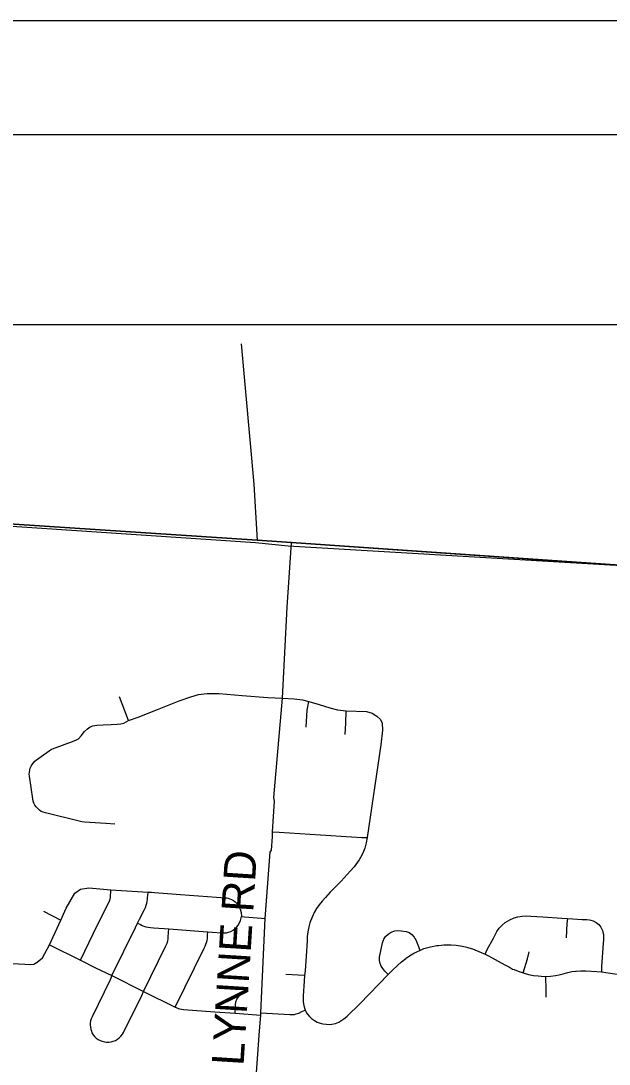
# Model space of a CAD drawing. Extents: x 1880545 to 1948545, y 79309 to 723051.
# Drawn here: x 1911747 to 1916920, y 713881 to 723051 of the extents above; entities that cross this region are included whole.
import ezdxf

# ---------------------------------------------------------------- set-up
doc = ezdxf.new("R2010")
doc.units = 0
for name, color, linetype in [('GM_X_Corporation', 7, 'Continuous'), ('GM_X_Township', 7, 'Continuous'), ('GM_X_Township_Road', 7, 'Continuous'), ('SH_Border', 7, 'Continuous'), ('SH_Cut_Line', 7, 'Continuous'), ('SH_Text', 7, 'Continuous')]:
    doc.layers.add(name, color=color, linetype=linetype)

msp = doc.modelspace()

# ---------------------------------------------------------------- linework, layer by layer
at = {"layer": 'GM_X_Corporation'}
msp.add_lwpolyline([(1919489.4, 720211.7), (1919365.4, 718089.3), (1918484.9, 718152.3), (1917524.9, 718231.9), (1914096.8, 718433.3), (1913810.1, 718462.2), (1910747.9, 718668), (1904355.4, 719097.5), (1898180.5, 719469.3), (1898145.1, 719477.4), (1897456.4, 719506.8), (1897439.2, 719506.5), (1897485.7, 720211.7)], dxfattribs=at)
at = {"layer": 'GM_X_Township'}
for points in [[(1919532.9, 720211.7), (1919386.9, 718084.6), (1918484.9, 718152.3), (1917524.9, 718231.9), (1914126, 718465.8), (1913825.7, 718485.3), (1910748.6, 718688), (1904377.2, 719098.9), (1899877.1, 719377.9), (1898145.1, 719477.4), (1897456.4, 719506.8), (1896833.7, 719533.1), (1896793, 719531.9), (1894774.7, 719644.4), (1893522.1, 719763.2), (1893081.4, 719771.3), (1891817.3, 719823), (1891843, 720211.7)], [(1899877.1, 719377.9), (1904377.2, 719098.9), (1910748.6, 718688), (1913825.7, 718485.3), (1914126, 718465.8), (1917524.9, 718231.9), (1918484.9, 718152.3), (1919386.9, 718084.6), (1922040.5, 717966.3)]]:
    msp.add_lwpolyline(points, dxfattribs=at)
at = {"layer": 'GM_X_Township_Road'}
for p, q in [((1914127.1, 718463), (1913826.9, 718482.5)), ((1917526.1, 718229.1), (1914127.1, 718463)), ((1912694.5, 716901.1), (1912612.8, 717111.1)), ((1911946.4, 715226.6), (1912098.8, 715147.2)), ((1914240.7, 714660.1), (1914076, 714670.3))]:
    msp.add_line(p, q, dxfattribs=at)
for points in [[(1913826.9, 718482.5), (1913797, 718979.1), (1913686.9, 720211.7)], [(1913826.9, 718482.5), (1910749.7, 718685.2), (1904378.3, 719096.1)], [(1913761, 712909.6), (1913763.9, 712961.6), (1913794.1, 713451), (1913818.8, 713807.7), (1913846, 714173.9), (1913855.9, 714310.9), (1913856.8, 714331.9), (1913895.8, 715162.1), (1913937.8, 715745.4), (1913951.2, 715762.5), (1913960.2, 715880), (1913960.2, 715924.2), (1913977.5, 716194), (1913972.6, 716223.4), (1914046.4, 717097.8), (1914089.2, 717898.5), (1914127.1, 718463)], [(1912016.4, 716649.2), (1912088.5, 716676.9), (1912159.7, 716701.2), (1912177.1, 716708), (1912229.4, 716727.7), (1912253.6, 716741.9), (1912277.8, 716766.9), (1912307.8, 716803.6), (1912331.9, 716827.7), (1912356.1, 716845.3), (1912380.3, 716854.4), (1912416.1, 716861.9), (1912470.3, 716862.7), (1912541.2, 716866.9), (1912593.6, 716869.4), (1912624.5, 716871.9), (1912651.2, 716878.6), (1912694.5, 716901.1), (1912779.5, 716931.1), (1912947.9, 716999.4), (1913139.6, 717074.5), (1913241.3, 717111.1), (1913309.6, 717129.4), (1913386.3, 717139.4), (1913489.6, 717139.4), (1913693, 717121.1), (1913919.7, 717104.4), (1914046.4, 717097.8)], [(1914046.4, 717097.8), (1914149.8, 717091.1), (1914224.8, 717084.5), (1914279.8, 717069.4), (1914369.8, 717042.8), (1914463.2, 717014.4), (1914531.5, 716994.4), (1914608.2, 716986.1), (1914786.6, 716981.1), (1914836.6, 716966.1), (1914878.3, 716941.1), (1914908.2, 716909.4), (1914923.2, 716879.4), (1914928.3, 716816.1), (1914911.6, 716687.7), (1914792.4, 715872.5), (1914782.6, 715825.7), (1914770.7, 715779.2), (1914754.6, 715735.6), (1914734.9, 715698), (1914721.8, 715677.1), (1914708.6, 715656.2), (1914677.6, 715615.7), (1914643, 715576.8), (1914563, 715490.9), (1914467.5, 715391.3), (1914424.5, 715345.3), (1914396.5, 715314.8), (1914370.2, 715280.8), (1914347.5, 715249.8), (1914326.7, 715215.2), (1914307.6, 715174), (1914287.2, 715123.3), (1914278.3, 715086.9), (1914270.5, 715043.9), (1914268.2, 715023), (1914265.8, 715002.1), (1914264.6, 714963.9), (1914254.6, 714830.4), (1914246.1, 714700.1), (1914240.7, 714660.1), (1914237.7, 714611.8), (1914230, 714481.7), (1914228.8, 714449.5), (1914230, 714428.6), (1914235.3, 714397.5), (1914245.5, 714356.3), (1914251.7, 714344.2), (1914264.3, 714324.1), (1914283.6, 714301.3), (1914302.2, 714283.5), (1914328.3, 714265.4), (1914353.6, 714250.8), (1914380, 714241.1), (1914403.3, 714235.2), (1914431.6, 714231.3), (1914463.2, 714231), (1914482.4, 714233.2), (1914512.5, 714239.8), (1914543, 714251.4), (1914560.3, 714260.4), (1914587.5, 714278), (1914599.4, 714288.3), (1914615.8, 714304.3), (1914727.3, 714410.9), (1914976.7, 714668.9), (1915015.4, 714707.3), (1915057.8, 714748.4), (1915093.6, 714780.1), (1915133.1, 714810.4), (1915139.5, 714815.3), (1915177.7, 714841.5), (1915203.4, 714855.6), (1915229, 714869.6), (1915255.3, 714880.9), (1915290.5, 714896.5), (1915350.2, 714912.6), (1915405.1, 714923.3), (1915419.2, 714924.8), (1915467.2, 714929.9), (1915495.8, 714931.1), (1915531.6, 714929.9), (1915575.8, 714926.9), (1915629.5, 714919.1), (1915668.9, 714910.2), (1915686.2, 714904.9), (1915717.9, 714895.3), (1915794.2, 714863.6), (1915828.7, 714848.4), (1915858.7, 714832), (1916001.4, 714752.6), (1916042.5, 714732.9), (1916071.2, 714717.4), (1916085.6, 714711.7), (1916119.5, 714698.3), (1916165.4, 714683.8), (1916211.4, 714669.7), (1916255.6, 714661.3), (1916296.2, 714656.5), (1916323.6, 714654.7), (1916359.9, 714650.9), (1916403, 714655.4), (1916448.4, 714661.3), (1916481.8, 714667.3), (1916515.2, 714675), (1916555.8, 714685.8), (1916591.6, 714694.7), (1916625.5, 714698.8), (1916631, 714699.5), (1916669.8, 714701.9), (1916714.6, 714700.7), (1916813, 714694.7), (1916853, 714691.7), (1917302.2, 714626.4)], [(1914254.8, 716842.7), (1914263.1, 716991.1), (1914279.8, 717069.4)], [(1914598.2, 716779.4), (1914603.7, 716878.8), (1914608.2, 716986.1)], [(1912574.1, 715989.9), (1912495.2, 715995.3), (1912307.3, 716008.1), (1912283.6, 716010.8), (1912260.2, 716015.5), (1911963.1, 716088.8), (1911944.3, 716094.8), (1911926.4, 716103.2), (1911909.8, 716113.9), (1911894.7, 716126.7), (1911881.4, 716141.4), (1911870.2, 716157.6), (1911861.2, 716175.2), (1911854.6, 716193.9), (1911850.6, 716213.2), (1911822.3, 716411.2), (1911820.8, 716429.4), (1911821.5, 716447.6), (1911824.5, 716465.5), (1911829.6, 716483), (1911836.7, 716499.8), (1911845.9, 716515.5), (1911856.9, 716530), (1911869.5, 716543.1), (1911883.7, 716554.6), (1912016.4, 716649.2)], [(1913960.2, 715924.2), (1914018.7, 715918.8), (1914745.6, 715872.9), (1914792.4, 715872.5)], [(1911672.5, 714765.2), (1911835.5, 714755.8), (1911860.6, 714761), (1911891, 714777.5), (1911938.4, 714814.8), (1911997.2, 714928.5), (1912098.8, 715147.2), (1912144.5, 715252.5), (1912221.8, 715383.8), (1912271.4, 715419.5), (1912344.8, 715429.5), (1912539.2, 715413.6), (1912864.9, 715393.9), (1912895.1, 715391.9), (1912920.6, 715390.8), (1913151.5, 715373.4), (1913544.9, 715344.4), (1913559.4, 715342.3), (1913568.5, 715340.5), (1913584.9, 715335.1), (1913600.2, 715328.5), (1913616.5, 715319.2), (1913630.8, 715308.4), (1913647.8, 715291.4), (1913660.2, 715275.5), (1913670.3, 715258.1), (1913678.4, 715236), (1913684.6, 715213.6), (1913686.5, 715178), (1913712, 715176.5), (1913863.7, 715164.1), (1913895.8, 715162.1)], [(1912271.1, 714793.6), (1912424.3, 715112), (1912527.8, 715320.4), (1912534.7, 715347.1), (1912539.2, 715413.6)], [(1912546.9, 714659.4), (1912755.8, 715081.7), (1912773.6, 715121.2), (1912791, 715154.8), (1912833.6, 715239.1), (1912841.7, 715257.3), (1912849, 715278), (1912853.9, 715294.8), (1912857.2, 715309.9), (1912859.8, 715328.1), (1912861.4, 715347.1), (1912863.4, 715364.9), (1912864.9, 715393.9)], [(1912773.6, 715121.2), (1912798.8, 715108.4), (1912814.3, 715100.7), (1912828.6, 715094.5), (1912844.6, 715088.6), (1912864.9, 715084), (1912888.1, 715081.3), (1912912.5, 715080.2), (1913008, 715072.8), (1913047.1, 715069.7), (1913085, 715067), (1913351.1, 715047.7), (1913391.4, 715044.6), (1913430, 715041.9), (1913514.8, 715035.7), (1913536, 715034.9), (1913556.5, 715036.5), (1913573.9, 715040.7), (1913594.4, 715048.4), (1913614.2, 715058.5), (1913632.7, 715072.8), (1913646.7, 715086.7), (1913658.6, 715103), (1913670.6, 715123.5), (1913678.8, 715143.2), (1913686.5, 715178)], [(1915828.7, 714848.4), (1915846.2, 714889.9), (1915902.3, 714989), (1915933.9, 715046.9), (1915953.6, 715074.9), (1915979.3, 715103), (1916006.7, 715125), (1916047.9, 715150.1), (1916084.9, 715166.2), (1916116, 715176.4), (1916155.9, 715182.4), (1916192.3, 715184.7), (1916231.1, 715182.4), (1916337.2, 715175.8), (1916503.9, 715165.6), (1916552.8, 715162.6), (1916601.2, 715159.1), (1916682.9, 715153.7), (1916724.7, 715151.9), (1916748.6, 715149.5), (1916758.3, 715146.6), (1916778.4, 715140.6), (1916806.5, 715125), (1916828.5, 715107.1), (1916847.1, 715085.1), (1916861.4, 715054.6), (1916867.5, 715028.2), (1916869.1, 715021.2), (1916870.3, 714987.8), (1916869.8, 714973), (1916868.5, 714943), (1916853.6, 714740.7), (1916853, 714691.7)], [(1916552.8, 715162.6), (1916547.7, 715117.2), (1916541.1, 714991.2)], [(1912825.7, 714520), (1913022, 714922), (1913032.8, 714945.2), (1913037.8, 714966.1), (1913040.9, 714981.5), (1913042.6, 714995.4), (1913045.2, 715039.9), (1913047.1, 715069.7)], [(1913102.6, 714381.5), (1913357.7, 714900.3), (1913366.2, 714917.7), (1913374, 714935.9), (1913379, 714949.8), (1913384, 714969.2), (1913386.7, 714986.6), (1913389.4, 715018.7), (1913391.4, 715044.6)], [(1914976.7, 714668.9), (1914948.5, 714698.3), (1914928.8, 714721.6), (1914915.7, 714741.3), (1914906.2, 714765.2), (1914900.2, 714790.8), (1914899.6, 714820.1), (1914927.7, 714947.8), (1914937.8, 714978.8), (1914953.9, 715003.3), (1914976, 715023), (1915003.5, 715040.3), (1915035.1, 715052.2), (1915063.1, 715055.8), (1915092.4, 715054), (1915135.9, 715046.9), (1915161, 715037.9), (1915185.5, 715020.6), (1915205.2, 714997.9), (1915212.6, 714986.3), (1915220.1, 714974.7), (1915243.4, 714916.2), (1915255.3, 714880.9)], [(1911997.2, 714928.5), (1912271.1, 714793.6), (1912404.4, 714729.1), (1912546.9, 714659.4), (1912825.7, 714520), (1913102.6, 714381.5), (1913141.7, 714366.9), (1913175.8, 714360.9), (1913453.7, 714341.1)], [(1916165.4, 714683.8), (1916201.9, 714807.5), (1916218, 714869)], [(1912546.9, 714659.4), (1912533.5, 714623.3), (1912372.7, 714297.1), (1912365.6, 714280.2), (1912360.4, 714262.5), (1912357.4, 714244.3), (1912356.6, 714225.9), (1912358, 714207.6), (1912361.5, 714189.5), (1912367.2, 714172), (1912371.9, 714157.1), (1912382.4, 714140.1), (1912395, 714124.6), (1912409.5, 714110.9), (1912425.6, 714099.2), (1912443.2, 714089.6), (1912461.8, 714082.3), (1912481.1, 714077.5), (1912501, 714075.3), (1912520, 714074.5), (1912540.4, 714076.7), (1912559.8, 714081.8), (1912578.6, 714089.9), (1912596, 714099.9), (1912611.7, 714112), (1912626.5, 714126), (1912639.4, 714143.8), (1912649, 714160.6), (1912810.3, 714484.8), (1912825.7, 714520)], [(1916359.9, 714650.9), (1916364, 714533.7), (1916363.4, 714468.5)], [(1913631, 714328.3), (1913633.6, 714381.2), (1913635.1, 714403.7), (1913638.2, 714429.2), (1913645.9, 714450.9), (1913662.2, 714476.5), (1913681.9, 714500.4), (1913743.7, 714553.4)], [(1913453.7, 714341.1), (1913631, 714328.3), (1913855.9, 714310.9)], [(1913856.8, 714331.9), (1914110.8, 714316.1), (1914126.5, 714316.1), (1914138.6, 714316.5), (1914152.6, 714318.6), (1914167.1, 714322.6), (1914190, 714329.8), (1914218.5, 714342.7), (1914245.5, 714356.3)]]:
    msp.add_lwpolyline(points, dxfattribs=at)
at = {"layer": 'SH_Border'}
msp.add_lwpolyline([(1883544.6, 722051.2), (1947544.6, 722051.2), (1947544.6, 680051.2), (1883544.6, 680051.2)], close=True, dxfattribs=at)
at = {"layer": 'SH_Cut_Line'}
msp.add_lwpolyline([(1880544.6, 679051.2), (1948544.6, 679051.2), (1948544.6, 723051.2), (1880544.6, 723051.2)], close=True, dxfattribs=at)
at = {"layer": 'SH_Text'}
msp.add_lwpolyline([(1884489.7, 720381.4), (1928140.8, 720381.4), (1928140.8, 691152), (1884489.7, 691152)], close=True, dxfattribs=at)

# ---------------------------------------------------------------- texts
msp.add_text('LYNNE RD', height=280, rotation=86.40079, dxfattribs=at).set_placement((1913704.6, 713861.8))

doc.saveas('drawing.dxf')
